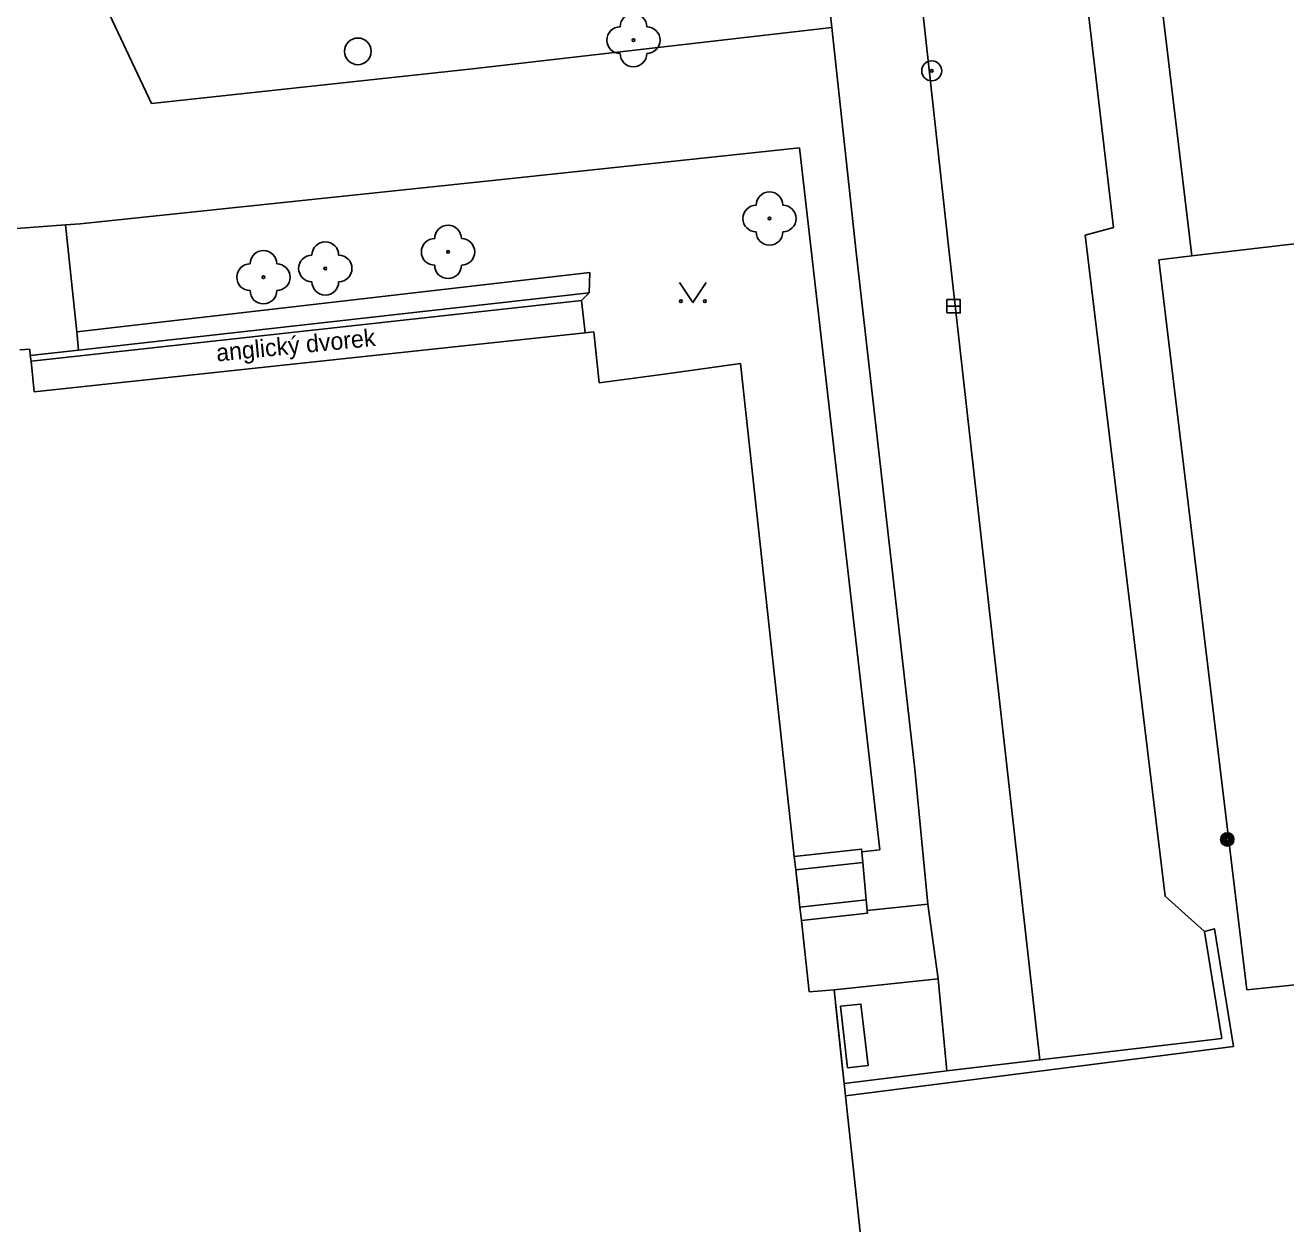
# Model space of a CAD drawing. Extents: x -539694 to -539148, y -1156467 to -1155920.
# Drawn here: x -539432.56 to -539385.31, y -1156100.87 to -1156055.63 of the extents above; entities that cross this region are included whole.
import ezdxf

# ---------------------------------------------------------------- set-up
doc = ezdxf.new("R2010")
doc.units = 0
for name, color, linetype in [('Vrstva 11', 7, 'Continuous'), ('Vrstva 21', 7, 'Continuous'), ('Vrstva 22', 7, 'Continuous'), ('Vrstva 25', 7, 'Continuous'), ('Vrstva 27', 7, 'Continuous'), ('Vrstva 36', 7, 'Continuous'), ('Vrstva 40', 7, 'Continuous'), ('Vrstva 5', 7, 'Continuous'), ('Vrstva 6', 7, 'Continuous')]:
    doc.layers.add(name, color=color, linetype=linetype)

msp = doc.modelspace()

# ---------------------------------------------------------------- linework, layer by layer
at = {"layer": 'Vrstva 11'}
for p, q in [((-539404.85, -1156033.16), (-539402.32, -1156055.71)), ((-539394.92, -1156036.03), (-539391.77, -1156063.21)), ((-539397.95, -1156063.92), (-539400.6, -1156039.68)), ((-539427.83, -1156058.57), (-539431.22, -1156051.37)), ((-539402.32, -1156055.71), (-539415.79, -1156057.26)), ((-539401.41, -1156064.14), (-539402.32, -1156055.71)), ((-539415.79, -1156057.26), (-539427.83, -1156058.57)), ((-539403.53, -1156060.23), (-539415.16, -1156061.47)), ((-539400.52, -1156086.55), (-539403.53, -1156060.23)), ((-539415.16, -1156061.47), (-539430.5, -1156063.08)), ((-539430.5, -1156063.08), (-539431.05, -1156063.11)), ((-539431.05, -1156063.11), (-539430.63, -1156067.13)), ((-539391.77, -1156063.21), (-539392.82, -1156063.5)), ((-539392.82, -1156063.5), (-539389.83, -1156088.28)), ((-539399.21, -1156083.53), (-539401.41, -1156064.14)), ((-539394.52, -1156094.42), (-539397.95, -1156063.92)), ((-539430.63, -1156067.13), (-539411.39, -1156064.9)), ((-539411.39, -1156064.9), (-539411.42, -1156065.67)), ((-539431.52, -1156068.14), (-539411.71, -1156065.95)), ((-539411.42, -1156065.67), (-539430.56, -1156067.81)), ((-539411.42, -1156065.67), (-539411.71, -1156065.95)), ((-539411.71, -1156065.95), (-539411.57, -1156067.17)), ((-539430.63, -1156067.13), (-539430.56, -1156067.81)), ((-539430.56, -1156067.81), (-539432.37, -1156068.01)), ((-539432.34, -1156068.23), (-539431.52, -1156068.14)), ((-539398.73, -1156088.59), (-539399.21, -1156083.53)), ((-539401.2, -1156086.62), (-539400.52, -1156086.55)), ((-539401.16, -1156087.02), (-539401.2, -1156086.62)), ((-539401.16, -1156087.02), (-539403.67, -1156087.3)), ((-539401.04, -1156088.42), (-539401.16, -1156087.02)), ((-539389.83, -1156088.28), (-539388.35, -1156089.61)), ((-539401.04, -1156088.42), (-539403.52, -1156088.7)), ((-539401, -1156088.82), (-539401.04, -1156088.42)), ((-539398.73, -1156088.59), (-539401, -1156088.82)), ((-539398.34, -1156091.38), (-539398.73, -1156088.59)), ((-539388.35, -1156089.61), (-539387.7, -1156093.62)), ((-539402.24, -1156091.8), (-539398.34, -1156091.38)), ((-539398.01, -1156094.83), (-539398.34, -1156091.38)), ((-539401.81, -1156095.77), (-539387.27, -1156093.92)), ((-539387.7, -1156093.62), (-539394.52, -1156094.42)), ((-539394.52, -1156094.42), (-539398.01, -1156094.83)), ((-539401.86, -1156095.31), (-539398.01, -1156094.83))]:
    msp.add_line(p, q, dxfattribs=at)
for points in [[(-539433.12, -1156064.25), (-539433.22, -1156063.28), (-539431.05, -1156063.11)], [(-539401.2, -1156086.62), (-539401.21, -1156086.52), (-539403.73, -1156086.8)], [(-539401, -1156088.82), (-539400.99, -1156088.92), (-539403.46, -1156089.2)], [(-539387.27, -1156093.92), (-539387.98, -1156089.51), (-539388.35, -1156089.61)], [(-539402, -1156092.41), (-539401.23, -1156092.33), (-539400.96, -1156094.63), (-539401.73, -1156094.72), (-539402, -1156092.41)]]:
    msp.add_lwpolyline(points, dxfattribs=at)
at = {"layer": 'Vrstva 21'}
for radius in [0.375, 0.05]:
    msp.add_circle((-539398.58, -1156057.34), radius, dxfattribs=at)
at = {"layer": 'Vrstva 22'}
for centre in [(-539409.76, -1156056.19), (-539404.66, -1156062.88), (-539416.71, -1156064.13), (-539423.63, -1156065.08), (-539421.31, -1156064.75)]:
    msp.add_circle(centre, 0.05, dxfattribs=at)
for centre, start, end in [((-539409.76, -1156055.69), 0, 180), ((-539410.26, -1156056.19), 90, 270), ((-539409.26, -1156056.19), 270, 90), ((-539409.76, -1156056.69), 180, 0), ((-539404.66, -1156062.38), 0, 180), ((-539405.16, -1156062.88), 90, 270), ((-539404.16, -1156062.88), 270, 90), ((-539416.71, -1156063.63), 0, 180), ((-539417.21, -1156064.13), 90, 270), ((-539416.21, -1156064.13), 270, 90), ((-539404.66, -1156063.38), 180, 0), ((-539423.63, -1156064.58), 0, 180), ((-539421.31, -1156064.25), 0, 180), ((-539424.13, -1156065.08), 90, 270), ((-539423.13, -1156065.08), 270, 90), ((-539421.81, -1156064.75), 90, 270), ((-539420.81, -1156064.75), 270, 90), ((-539416.71, -1156064.63), 180, 0), ((-539423.63, -1156065.58), 180, 0), ((-539421.31, -1156065.25), 180, 0)]:
    msp.add_arc(centre, 0.5, start, end, dxfattribs=at)
at = {"layer": 'Vrstva 25'}
for radius in [0.25, 0.2, 0.15, 0.1, 0.05]:
    msp.add_circle((-539387.497, -1156086.158), radius, dxfattribs=at)
at = {"layer": 'Vrstva 27'}
msp.add_line((-539398.01, -1156066.17), (-539397.51, -1156066.17), dxfattribs=at)
msp.add_lwpolyline([(-539398.01, -1156066.42), (-539397.51, -1156066.42), (-539397.51, -1156065.92), (-539398.01, -1156065.92)], close=True, dxfattribs=at)
msp.add_circle((-539420.09, -1156056.61), 0.5, dxfattribs=at)
at = {"layer": 'Vrstva 36'}
msp.add_lwpolyline([(-539408.03, -1156065.28), (-539407.53, -1156066.03), (-539407.03, -1156065.28)], dxfattribs=at)
for centre in [(-539407.98, -1156065.98), (-539407.081, -1156065.98)]:
    msp.add_circle(centre, 0.05, dxfattribs=at)
at = {"layer": 'Vrstva 5'}
for p, q in [((-539388.83, -1156064.28), (-539391.31, -1156043.51)), ((-539388.83, -1156064.28), (-539373.15, -1156062.45)), ((-539390.065, -1156064.424), (-539388.83, -1156064.28)), ((-539386.77, -1156091.8), (-539390.065, -1156064.424)), ((-539411.57, -1156067.17), (-539432.22, -1156069.38)), ((-539411.24, -1156067.13), (-539411.57, -1156067.17)), ((-539411.04, -1156069.04), (-539411.24, -1156067.13)), ((-539432.76, -1156067.8), (-539432.39, -1156067.78)), ((-539432.39, -1156067.78), (-539432.37, -1156068.01)), ((-539432.34, -1156068.23), (-539432.37, -1156068.01)), ((-539432.22, -1156069.38), (-539432.34, -1156068.23)), ((-539405.75, -1156068.32), (-539408.61, -1156068.71)), ((-539403.73, -1156086.8), (-539405.75, -1156068.32)), ((-539408.61, -1156068.71), (-539411.04, -1156069.04)), ((-539403.73, -1156086.8), (-539403.67, -1156087.3)), ((-539403.67, -1156087.3), (-539403.52, -1156088.7)), ((-539403.52, -1156088.7), (-539403.46, -1156089.2)), ((-539403.46, -1156089.2), (-539403.17, -1156091.87)), ((-539383.69, -1156091.48), (-539386.77, -1156091.8)), ((-539403.17, -1156091.87), (-539402.24, -1156091.8)), ((-539402.24, -1156091.8), (-539401.86, -1156095.31)), ((-539401.86, -1156095.31), (-539401.81, -1156095.77)), ((-539401.81, -1156095.77), (-539401.26, -1156100.87))]:
    msp.add_line(p, q, dxfattribs=at)
at = {"layer": 'Vrstva 6'}
for p, q in [((-539403.55, -1156088.36), (-539403.66, -1156087.42)), ((-539401.91, -1156094.89), (-539402.19, -1156092.3)), ((-539401.26, -1156100.87), (-539401.52, -1156098.43))]:
    msp.add_line(p, q, dxfattribs=at)

# ---------------------------------------------------------------- texts
at = {"layer": 'Vrstva 40'}
msp.add_text('anglický dvorek', height=0.65, rotation=5.6328, dxfattribs=at).set_placement((-539425.37, -1156068.24))

doc.saveas('drawing.dxf')
